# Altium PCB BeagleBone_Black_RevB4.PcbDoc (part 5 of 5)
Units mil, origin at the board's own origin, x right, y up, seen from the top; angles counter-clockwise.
Board outline 3401 x 2151 mil, 6 copper layers (TOP, LYR2_GND, LYR3, LYR4, LYR5_PWR, BOTTOM), stack 62 mil thick; 381 components, 310 nets, 1705 pads, 850 vias.
Unrouted connection lines stored in the file: 1.
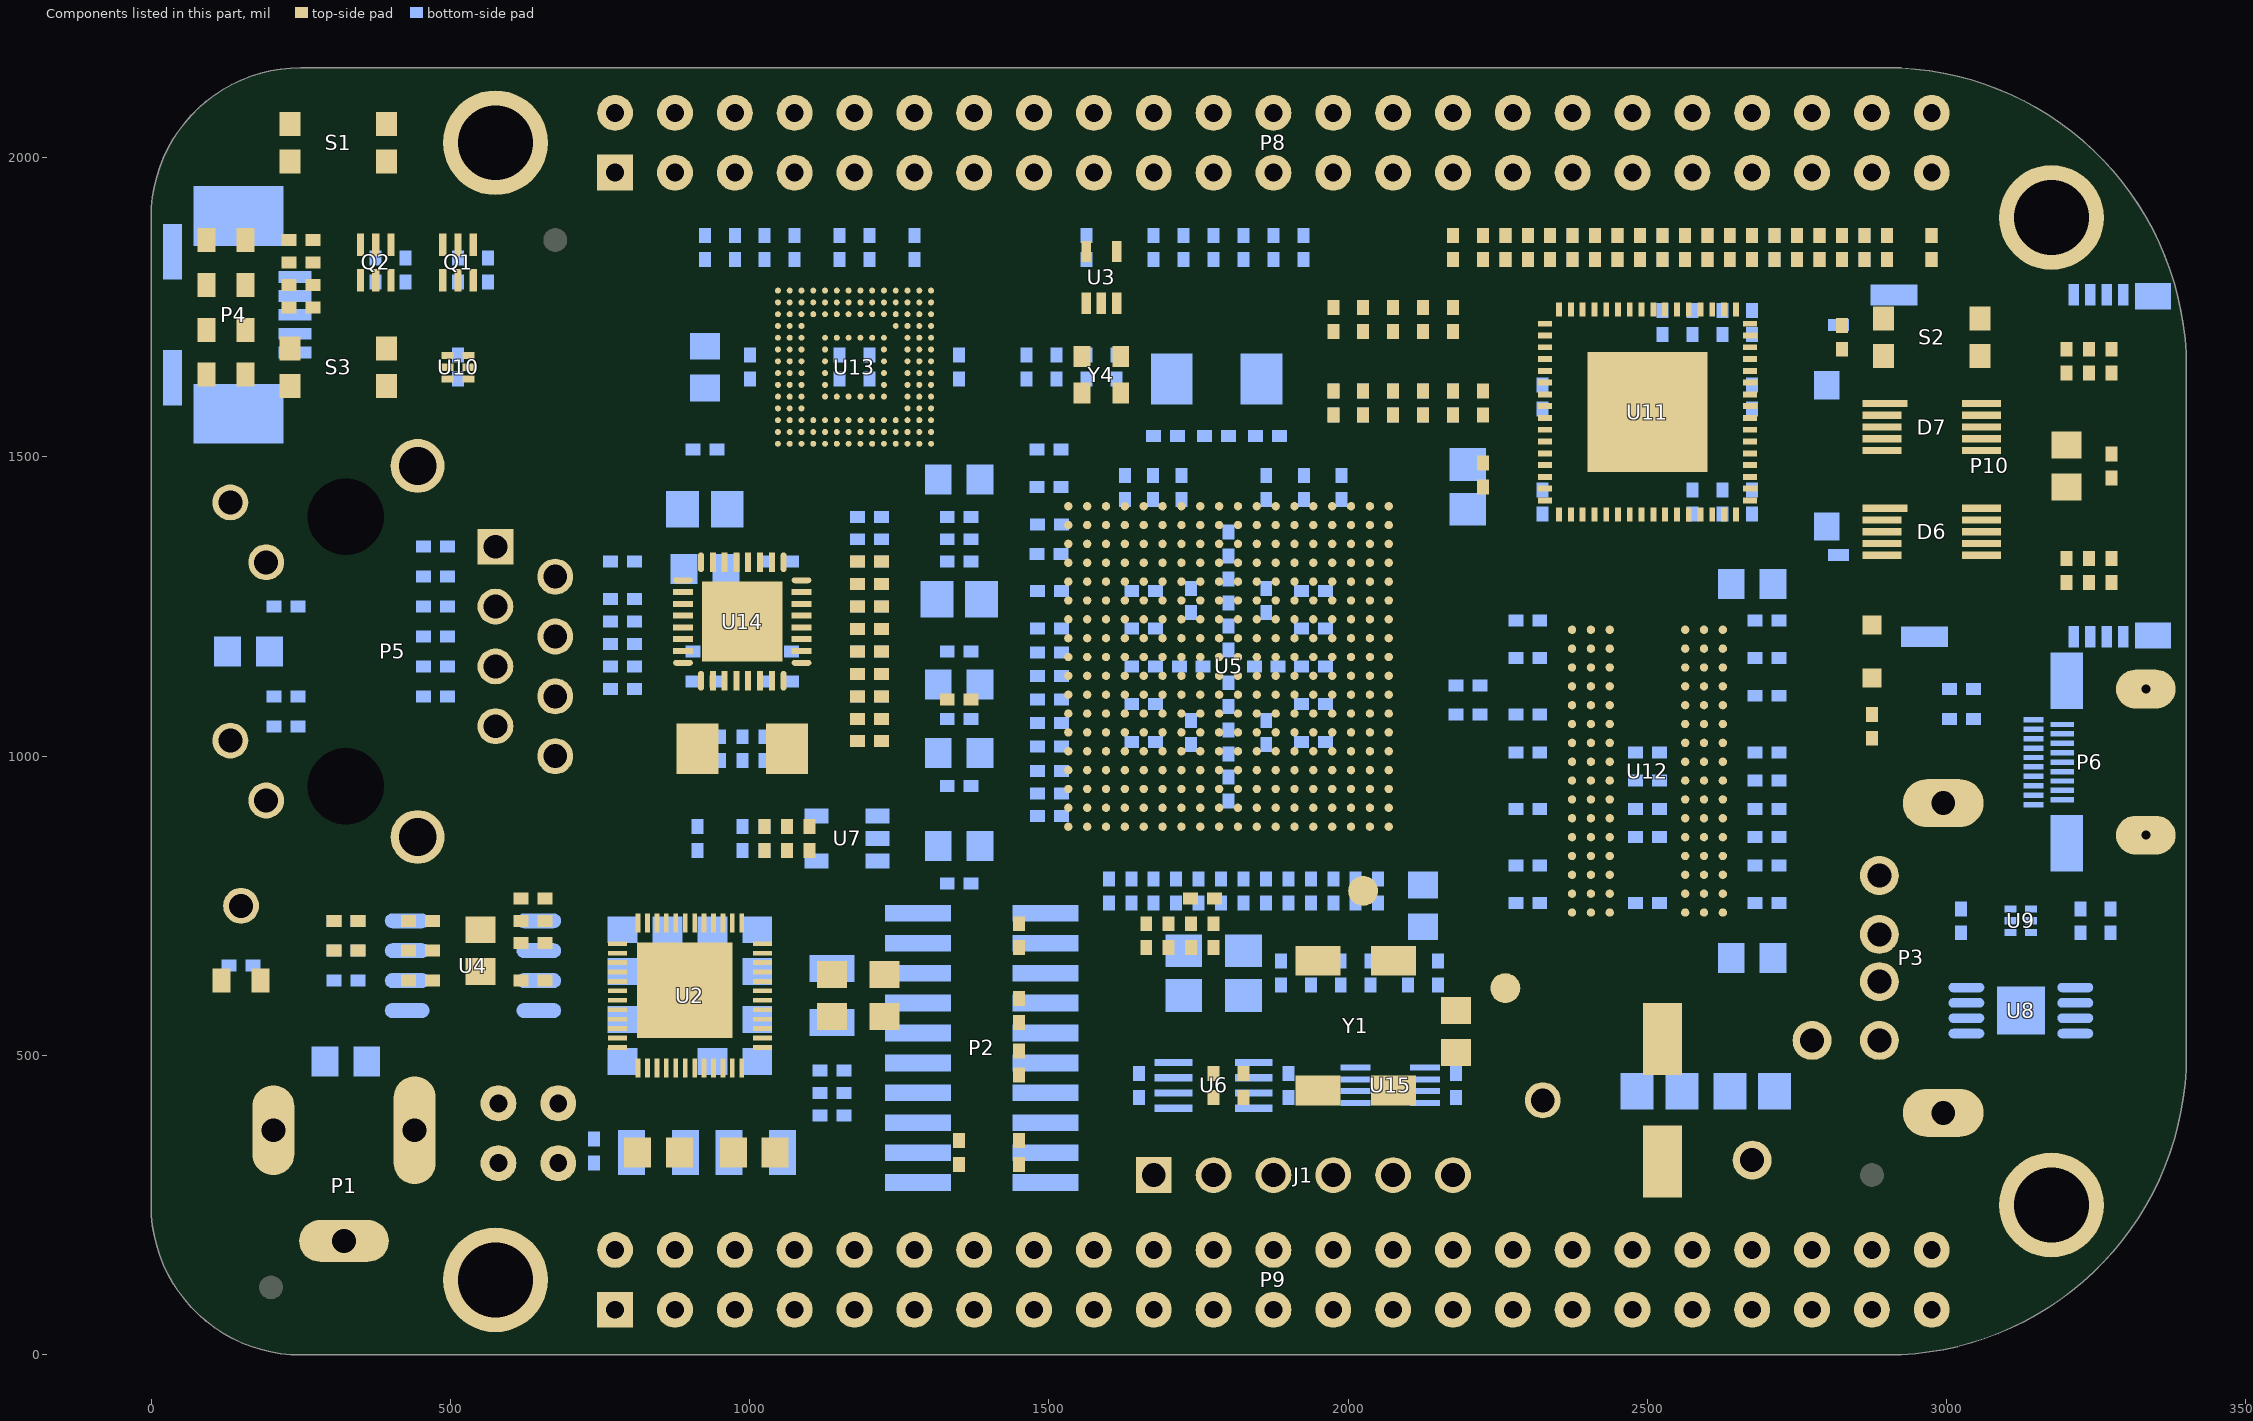
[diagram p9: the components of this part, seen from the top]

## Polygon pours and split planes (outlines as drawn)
no net on Bottom Overlay "Bottom Overlay-No Net" (solid): 47 vertices, not listed, extent 539.79,828.78 590.56,915.78
no net on Bottom Overlay "Bottom Overlay-No Net" (solid): 33 vertices, not listed, extent 603.12,829.78 668.46,915.78
no net on Bottom Overlay "Bottom Overlay-No Net" (solid): 704.91,870.75 ccw(c608.27,870.75) 608.27,967.39 ccw(c608.27,870.75) 511.63,870.75 ccw(c608.27,870.75) 608.27,774.11 ccw(c608.27,870.75) 704.91,870.75
no net on Bottom Overlay "Bottom Overlay-No Net" (solid): 2177.5,492.5 2727.5,492.5 2727.5,617.5 2177.5,617.5 2177.5,492.5
no net on TITLE_BLOCK "TITLE_BLOCK-No Net" (solid): 3550,-50 3450,-50 3450,-150 3400,-150 3400,0 3550,0 3550,-50
no net on TITLE_BLOCK "TITLE_BLOCK-No Net" (solid): 3450,2300 3450,2200 3550,2200 3550,2150 3400,2150 3400,2300 3450,2300
no net on TITLE_BLOCK "TITLE_BLOCK-No Net" (solid): -150,2200 -50,2200 -50,2300 0,2300 0,2150 -150,2150 -150,2200
no net on TITLE_BLOCK "TITLE_BLOCK-No Net" (solid): -50,-150 -50,-50 -150,-50 -150,0 0,0 0,-150 -50,-150
GND_EARTH on BOTTOM "BOTTOM-GND_EARTH" (solid, remove dead copper, pour order 2098): 92 vertices, not listed, extent 25,25 3375,2125
VDDS on BOTTOM "BOTTOM-VDDS 3" (solid, pour order 1441): 107 vertices, not listed, extent 1825,1300 1885,1435
VDDS on BOTTOM "BOTTOM-VDDS 4" (solid, pour order 1442): 212 vertices, not listed, extent 1515,890 1655,1035
VDD_3V3B on BOTTOM "BOTTOM-VDD_3V3B 28" (solid, pour order 2053): 29 vertices, not listed, extent 950,1320.2 1037.5,1437.5
VDD_3V3A on BOTTOM "BOTTOM-VDD_3V3A 24" (solid, pour order 2120): 111 vertices, not listed, extent 1650,1300 1710,1435
VDD_3V3A on BOTTOM "BOTTOM-VDD_3V3A 25" (solid, pour order 2121): 236 vertices, not listed, extent 1890,1300 1998.29,1435
VDD_3V3A on BOTTOM "BOTTOM-VDD_3V3A 26" (solid, pour order 2123): 96 vertices, not listed, extent 1520,1085 1650,1170
VDD_PLL on BOTTOM "BOTTOM-VDD_PLL" (solid, pour order 2296): 167 vertices, not listed, extent 1870,790 1920,1000
VDD_PLL on BOTTOM "BOTTOM-VDD_PLL 1" (solid, pour order 2298): 76 vertices, not listed, extent 1711.26,1300 1775,1435
VDD_PLL on BOTTOM "BOTTOM-VDD_PLL 2" (solid, pour order 2299): 62 vertices, not listed, extent 1515,1065 1615,1110
GND_OSC0 on BOTTOM "BOTTOM-GND_OSC0" (solid, pour order 2604): 31 vertices, not listed, extent 1640,1530 1920,1700
DGND on BOTTOM "BOTTOM-DGND" (solid, pour order 2617): 1625,1200 1630,1205 1630,1220 1650,1220 1650,1205 1660,1195 1660,1170 1650,1160 1650,1145 1625,1145 1625,1200
DGND on BOTTOM "BOTTOM-DGND 1" (solid, pour order 2618): 46 vertices, not listed, extent 770,472.5 1035,642.5
GND_OSC1 on TOP "TOP-GND_OSC1" (solid, pour order 2562): 169 vertices, not listed, extent 1900,390 2125,710
VDD_5V on TOP "TOP-VDD_5V" (solid, pour order 2318): 430,360 410,380 410,528.88 430,548.88 758.4,548.9 758.4,540.9 752.3,540.9 691.45,480 530,480 510,460 510,380 490,360
GND_EARTH on TOP "TOP-GND_EARTH" (solid, remove dead copper, pour order 2089): 91 vertices, not listed, extent 25,25 3375,2125
VDCDC1 on TOP "TOP-VDCDC1" (solid, pour order 1461): 18 vertices, not listed, extent 780,375 911.8,479.82
VDD_MPU on TOP "TOP-VDD_MPU 6" (solid, pour order 2144): 992.5,462.5 985,462.5 985,487.5 1012.5,487.5 1045,455 1100,455 1100,440 1075,415 1075,340 1065,330 1035,330 1020,345 1020,435 992.5,462.5
P_L3 on TOP "TOP-P_L3" (solid, pour order 2228): 18 vertices, not listed, extent 1020,600 1160,700
P_L2 on TOP "TOP-P_L2" (solid, pour order 2246): 970,375 960,385 960,420 965,425 965,439.42 966.14,440.56 966.14,452.36 970.25,456.48 973.52,456.48 1005,425 1005,385 995,375 970,375
P_L1 on TOP "TOP-P_L1" (solid, pour order 2268): 935,437.5 935,385 925,375 880,375 870,385 870,395 875,400 890,400 912.76,422.76 912.76,435.26 925,447.5 935,437.5
VDD_CORE on TOP "TOP-VDD_CORE" (solid, pour order 2466): 28 vertices, not listed, extent 1020,500 1240,584.72
DGND on TOP "TOP-DGND" (solid, pour order 2619): 21 vertices, not listed, extent 1525,1550 1650,1720
VDDS_DDR on LYR3 "LYR3-VDDS_DDR" (solid, pour order 1574): 382 vertices, not listed, extent 725,100 2375,340
VDD_MPU on LYR3 "LYR3-VDD_MPU" (solid, pour order 2143): 375 vertices, not listed, extent 1410,820 1790,1064.98
VDD_1V8 on LYR3 "LYR3-VDD_1V8" (solid, pour order 2377): 134 vertices, not listed, extent 1290,1270 1660,1360
VDD_CORE on LYR3 "LYR3-VDD_CORE" (solid, pour order 2465): 810 vertices, not listed, extent 1260,940 1945,1325
VRTC on LYR3 "LYR3-VRTC" (solid, pour order 2541): 104 vertices, not listed, extent 1855,815 1945,970
VRTC on LYR5_PWR "LYR5_PWR-VRTC" (solid, remove dead copper, pour order 2128): 1855,810 1865,800 1950,800 1970,820 1970,962.5 1957.5,975 1865,975 1855,965
VDDS on LYR5_PWR "LYR5_PWR-VDDS 2" (solid, remove dead copper, pour order 2126): 1630,985 1635,980 1665,980 1695,1010 1840,1010 1845,1015 1845,1050 1820,1075 1685,1075 1670,1060 1670,1040 1630,1000
VDD_PLL on LYR5_PWR "LYR5_PWR-VDD_PLL" (solid, remove dead copper, pour order 2124): 19 vertices, not listed, extent 1600,985 1935,1140
HDMI_1V8 on LYR5_PWR "LYR5_PWR-HDMI_1V8" (solid, pour order 2122): 2130,1370 2130,1755 2140,1765 2330,1765 2365,1800 2675,1800 2710,1765 2760,1765 2770,1755 2770,1370 2760,1360 2140,1360
VDD_1V8 on LYR5_PWR "LYR5_PWR-VDD_1V8 1" (solid, pour order 2119): 17 vertices, not listed, extent 1040,680 1330,1350
VDD_PHYA on LYR5_PWR "LYR5_PWR-VDD_PHYA" (solid, remove dead copper, pour order 2117): 21 vertices, not listed, extent 75,875 920,1475
VDDS_DDR on LYR5_PWR "LYR5_PWR-VDDS_DDR" (solid, pour order 2114): 19 vertices, not listed, extent 1945,212.5 2775,1350
VDD_1V8 on LYR5_PWR "LYR5_PWR-VDD_1V8" (solid, pour order 2111): 1760,550 1760,990 1770,1000 1840,1000 1845,995 1845,805 1860.5,789.5 1925.5,789.5 1935,780 1935,550 1925,540 1770,540
SYS_5V on LYR5_PWR "LYR5_PWR-SYS_5V" (solid, pour order 2109): 29 vertices, not listed, extent 1025,50 3312.5,962.5
VDD_3V3A on LYR5_PWR "LYR5_PWR-VDD_3V3A" (solid, pour order 2106): 77 vertices, not listed, extent 840,210 2890,1865
VDD_3V3B on LYR5_PWR "LYR5_PWR-VDD_3V3B" (solid, remove dead copper, pour order 2104): 87 vertices, not listed, extent 75,50 3312.5,2100
GND_EARTH on LYR5_PWR "PWR-GND_EARTH" (solid, pour order 2096): 91 vertices, not listed, extent 25,25 3375,2125
VDDS on LYR4 "LYR4-VDDS" (solid, pour order 1440): 569 vertices, not listed, extent 1800,945 1945,1369.98
VDD_PLL on LYR4 "LYR4-VDD_PLL" (solid, pour order 2297): 157 vertices, not listed, extent 1510,1065 1619.98,1250
VDD_1V8 on LYR4 "LYR4-VDD_1V8" (solid, pour order 2376): 1247 vertices, not listed, extent 1565,980 2170,1440
DGND on LYR2_GND "GND-DGND" (solid, remove dead copper, pour order 2101): 77 vertices, not listed, extent 75,50 3312.5,2100
GND_EARTH on LYR2_GND "GND-GND_EARTH" (solid, pour order 2091): 91 vertices, not listed, extent 25,25 3375,2125

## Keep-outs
TOP:
  circle w1: c675,1862.5 r62.5
  circle w1: c2875,300 r62.5
  circle w1: c200,112.5 r62.5
BOTTOM:
  circle w1: c2875,300 r62.5
  circle w1: c675,1862.5 r62.5
  circle w1: c200,112.5 r62.5

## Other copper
TOP:
  rectangle net GND_EARTH: 3325,1637.5 3375,1657.5
  text "LAYER 1" at 1000,-700 h55
  text "COMPONENT" at 1000,-800 h55
LYR2_GND:
  rectangle net GND_EARTH: 3325,1637.5 3375,1657.5
  text "LAYER 2" at 1000,-700 h55
  text "GROUND" at 1000,-800 h55
LYR3:
  text "LAYER 3" at 1000,-700 h55
  text "SIGNAL" at 1000,-800 h55
LYR4:
  text "LAYER 4" at 1000,-700 h55
  text "SIGNAL" at 1000,-800 h55
LYR5_PWR:
  rectangle: 3325,1637.5 3375,1657.5
  text "LAYER 5" at 1000,-700 h55
  text "POWER" at 1000,-800 h55
BOTTOM:
  rectangle net GND_EARTH: 45,1884.5 81,1952.9
  rectangle net GND_EARTH: 3325,1645 3375,1665
  text "PCB RevB4" at 87.5,212.5 h40 r270
  text "LAYER 6" at 1000,-700 h55
  text "SOLDER" at 1000,-800 h55
Multi-Layer:
  lines w1: 343.7,-768.7 275,-700 364.5,-610.5 ; 346.8,-864.2 ccw(c357.67,-864.2) 349.9,-871.8 ; 347,-864.2 347,-756.2 ; 347,-862.5 347,-756.2 ; 350,-871.7 374.5,-896.5 ; 374.4,-896.6 ccw(c390.5,-880.26) 390.5,-903.2 ; 378.2,-803 425,-850 575,-700 425,-550 386.5,-588.5 ; 390,-903 462.5,-903 390.5,-903 ; 425,-903 425,-950 ; 425,-871.7 425,-643.7 ; 425,-609.2 425,-515.5 ; 425,-484.2 425,-450 ; 434.5,-609.2 453,-609.2 ; 437.5,-640.5 453,-640.5 ; 453,-515.7 ccw(c453,-500) 468.7,-500 ccw(c453,-500) 453,-484.3 ; 462.5,-903.2 ccw(c462.5,-887.5) 478.2,-887.5 ccw(c462.5,-887.5) 462.5,-871.8 ; 175,-700 675,-700 ; 175,-700 425,-450 ; 175,-700 425,-950 ; 347,-756.2 368.7,-734.2 ; 347,-756.2 368.7,-734.2 ; 368.7,-734.2 378.2,-734.2 ; 368.7,-734.2 378.2,-734.2 ; 378.2,-856.2 378.2,-734.2 ; 378.2,-856.2 393.7,-871.7 ; 378.2,-856.2 393.7,-871.7 ; 378.2,-856.2 378.2,-734.2 ; 378.2,-581.2 378.2,-543.7 ; 378.2,-581.2 406.2,-609.2 ; 378.2,-581.2 378.2,-543.7 ; 378.2,-581.2 406.2,-609.2 ; 378.2,-543.7 406.2,-515.5 ; 378.2,-543.7 406.2,-515.5 ; 393.7,-871.7 462.5,-871.7 393.7,-871.7 ; 406.2,-609.2 453,-609.2 ; 406.2,-609.2 453,-609.2 ; 406.2,-515.5 453,-515.5 406.2,-515.5 ; 425,-950 675,-700 ; 425,-450 675,-700 ; 453,-640.5 403.2,-640.5 453,-640.5 ; 468.7,-625 cw(c453,-625) 453,-640.7 ccw(c453,-625) 468.7,-625 ; 468.7,-625 ccw(c453,-625) 453,-609.3 cw(c453,-625) 468.7,-625 ; 346.8,-589.2 ccw(c357.67,-589.2) 349.9,-596.8 cw(c357.67,-589.2) 346.8,-589.2 ; 346.8,-540.5 cw(c369.74,-540.5) 353.4,-524.4 ccw(c369.74,-540.5) 346.8,-540.5 ; 347,-589.2 347,-540.5 347,-589.2 ; 350,-700 425,-625 500,-700 425,-775 350,-700 ; 350,-596.7 387.2,-634 350,-596.7 ; 353.5,-524.5 387.5,-490.5 353.5,-524.5 ; 387.1,-634.1 ccw(c403.2,-617.76) 403.2,-640.7 cw(c403.2,-617.76) 387.1,-634.1 ; 387.6,-490.6 cw(c402.5,-505.75) 402.5,-484.5 ccw(c402.5,-505.75) 387.6,-490.6 ; 402.5,-484.2 453,-484.2 402.5,-484.2
  lines w20: -5.1,-1127.9 3419.9,-1127.9 ; -5.1,-1127.9 -5.1,-302.9 ; -5.1,-1127.9 3419.9,-1127.9 ; -5.1,-1127.9 -5.1,-302.9 ; -5.1,-302.9 3419.9,-302.9 ; -5.1,-302.9 3419.9,-302.9 ; 3419.9,-1127.9 3419.9,-302.9 ; 3419.9,-1127.9 3419.9,-302.9 ; 894.9,-1127.9 894.9,-302.9 894.9,-1127.9 ; 894.9,-852.9 3419.9,-852.9 894.9,-852.9 ; 894.9,-577.9 3419.9,-577.9 894.9,-577.9 ; 1669.9,-852.9 1669.9,-577.9 1669.9,-852.9
  lines w30: 275,-762.5 362.5,-762.5 362.5,-700 425,-637.5 487.5,-700 487.5,-762.5 562.5,-762.5 ; 312.5,-762.5 262.5,-762.5 225,-725 225,-675 262.5,-637.5 312.5,-637.5 ; 362.5,-725 487.5,-725 ; 512.5,-637.5 550,-637.5 ; 537.5,-762.5 537.5,-637.5 587.5,-637.5 625,-675 625,-725 587.5,-762.5 537.5,-762.5
  text "Circuit Co." at 994.9,-502.9 h100
  text "Circuit Co." at 994.9,-502.9 h100
  text "BeagleBone Black Rev B4" at 1725,-750 h75
  text "BeagleBone Black Rev B4" at 1725,-750 h75
  text "DATE:" at 1025,-1055 h100
  text "DATE:" at 1025,-1055 h100
  text "04/02/2013" at 1600,-1055 h100
  text "04/02/2013" at 1600,-1055 h100

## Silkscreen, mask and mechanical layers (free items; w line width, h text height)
Top Overlay:
  lines w5: 1175,0 1175,37.5 ; 1175,212.5 1175,250 ; 1175,1900 1175,1937.5 ; 1175,2112.5 1175,2150 ; 1250,1075 1300,1125 ; 1250,1300 1300,1350 ; 1675,0 1675,37.5 ; 1675,212.5 1675,250 ; 1675,1900 1675,1937.5 ; 1675,2112.5 1675,2150 ; 2175,0 2175,37.5 ; 2175,212.5 2175,250 ; 2175,1900 2175,1937.5 ; 2175,2112.5 2175,2150 ; 2675,0 2675,37.5 ; 2675,212.5 2675,250 ; 2675,1900 2675,1937.5 ; 2675,2112.5 2675,2150
  text "RESET" at 290,2095 h28
  text "USER LEDS" at 15,1915 h28
  text "0" at 25,1830 h28
  text "1" at 25,1755 h28
  text "2" at 25,1680 h28
  text "3" at 25,1605 h28
  text "POWER" at 295,1550 h28
  text "USB" at 25,1525 h40
  text "AM335x" at 1870,1455 h40
  text "microSD Card" at 3375,1255 h40 r90
  text "HDMI" at 3225,987.5 h40
  text "10/100 Ethernet" at 820,875 h40 r90
  text "PWR" at 62.5,587.5 h28 r90
  text "USB Host" at 3065,355 h40
  text "TSLK" at 1000,-750 h80
  text "TSLKC" at 1000,-750 h80
Bottom Overlay:
  drawing of 2121 lines, arcs and shapes, not listed
  text "S/N" at 2850,570 h40
  text "BSLK" at 1000,-750 h80
  text "BSLKC" at 1000,-750 h80
Top Solder:
  text "SMC" at 1000,-750 h80
Bottom Solder:
  text "SMS" at 1000,-750 h80
FAB:
  drawing of 1884 lines, arcs and shapes, not listed
  text "DRILL CHART: TOP to BOTTOM" at 320,6027.5 h125
  text "ALL UNITS ARE IN MILS" at 795,5847.5 h100
  text "FIGURE" at -925,5712.5 h100
  text "SIZE" at 265,5712.5 h100
  text "TOLERANCE" at 1575,5712.5 h100
  text "PLATED" at 2955,5712.5 h100
  text "QTY" at 3885,5712.5 h100
  text "6.0" at 260,5527.5 h125
  text "+3.0/-3.0" at 1470,5527.5 h125
  text "PLATED" at 2880,5527.5 h125
  text "27" at 3890,5527.5 h125
  text "8.0" at 260,5317.5 h125
  text "+3.0/-3.0" at 1470,5317.5 h125
  text "PLATED" at 2880,5317.5 h125
  text "794" at 3840,5317.5 h125
  text "12.0" at 210,5107.5 h125
  text "+3.0/-3.0" at 1470,5107.5 h125
  text "PLATED" at 2880,5107.5 h125
  text "30" at 3890,5107.5 h125
  text "30.0" at 210,4897.5 h125
  text "+3.0/-3.0" at 1470,4897.5 h125
  text "PLATED" at 2880,4897.5 h125
  text "96" at 3890,4897.5 h125
  text "40.0" at 210,4687.5 h125
  text "+3.0/-3.0" at 1470,4687.5 h125
  text "PLATED" at 2880,4687.5 h125
  text "26" at 3890,4687.5 h125
  text "63.0" at 210,4477.5 h125
  text "+3.0/-3.0" at 1470,4477.5 h125
  text "PLATED" at 2880,4477.5 h125
  text "2" at 3940,4477.5 h125
  text "125.0" at 160,4267.5 h125
  text "+3.0/-3.0" at 1470,4267.5 h125
  text "PLATED" at 2880,4267.5 h125
  text "4" at 3940,4267.5 h125
  text "128.0" at 160,4057.5 h125
  text "+5.0/-5.0" at 1470,4057.5 h125
  text "NON-PLATED" at 2680,4057.5 h125
  text "2" at 3940,4057.5 h125
  text "50.0x15.0" at -40,3847.5 h125
  text "+3.0/-3.0" at 1470,3847.5 h125
  text "PLATED" at 2880,3847.5 h125
  text "2" at 3940,3847.5 h125
  text "95.0x40.0" at -40,3637.5 h125
  text "+3.0/-3.0" at 1470,3637.5 h125
  text "PLATED" at 2880,3637.5 h125
  text "2" at 3940,3637.5 h125
  text "120.0x40.0" at -90,3427.5 h125
  text "+3.0/-3.0" at 1470,3427.5 h125
  text "PLATED" at 2880,3427.5 h125
  text "1" at 3940,3427.5 h125
  text "120.0x40.0" at -90,3217.5 h125
  text "+3.0/-3.0" at 1470,3217.5 h125
  text "PLATED" at 2880,3217.5 h125
  text "1" at 3940,3217.5 h125
  text "140.0x40.0" at -90,3007.5 h125
  text "+3.0/-3.0" at 1470,3007.5 h125
  text "PLATED" at 2880,3007.5 h125
  text "1" at 3940,3007.5 h125
  text "APPROVED" at 11530.1,-7272.1 h100
  text "CIRCUITCO." at 14994.9,-7452.9 h175
  text "CIRCUITCO." at 14994.9,-7452.9 h175
  text "CHECKED" at 11530.1,-7522.1 h100
  text "CalCad" at 12910,-7770 h100
  text "CalCad" at 12910,-7770 h100
  text "DRAFTING" at 11530.1,-7772.1 h100
  text "DATE" at 8505.1,-8022.1 h100
  text "ENGR" at 11530.1,-8022.1 h100
  text "04/02/13" at 9950,-8025 h100
  text "04/02/13" at 9950,-8025 h100
  text "FABRICATION DRAWING," at 14094.9,-8052.9 h150
  text "FABRICATION DRAWING," at 14094.9,-8052.9 h150
  text "DESIGN ENGR" at 8505.1,-8272.1 h100
  text "BeagleBone Black" at 14094.9,-8352.9 h150
  text "BeagleBone Black" at 14094.9,-8352.9 h150
  text "PROJECT ENGR" at 8505.1,-8522.1 h100
  text "ENGR MGR" at 8505.1,-8772.1 h100
  text "NONE" at 14880.1,-8772.1 h100
  text "PCB REV B4" at 16394.9,-8952.9 h150
  text "PCB REV B4" at 16394.9,-8952.9 h150
  text "NEXT ASSEMBLY" at 9230.1,-9022.1 h100
  text "1 OF 1" at 14880.1,-9022.1 h100
ASSY:
  drawing of 15196 lines, arcs and shapes, not listed
  text "RESET" at -9928,9502.64 h80
  text "2" at -8338,9372.64 h80
  text "46" at 1062,9372.64 h80
  text "46" at 4858.68,9372.64 h80
  text "2" at 14368.68,9372.64 h80
  text "1" at -9388,9322.64 h80
  text "S1" at -10688,9172.64 h150
  text "P8" at 1062,9122.64 h150
  text "P8" at 4758.68,9122.64 h150
  text "P4" at 16468.68,9002.64 h150
  text "1" at -8338,8922.64 h80
  text "45" at 1062,8922.64 h80
  text "45" at 4858.68,8922.64 h80
  text "1" at 14368.68,8922.64 h80
  text "R72" at -9908,8802.64 h80
  text "USER LEDS" at -11028,8782.64 h80
  text "R95" at 52,8702.64 h80
  text "R103" at 12906.68,8685.32 h80
  text "R73" at -9908,8662.64 h80
  text "P" at -6948,8662.64 h80
  text "A" at -5928,8662.64 h80
  text "D2" at -11048,8592.64 h80
  text "R77" at 15028.68,8552.64 h80 r90
  text "R76" at 15228.68,8552.64 h80 r90
  text "R79" at 15568.68,8552.64 h80 r90
  text "R78" at 15768.68,8552.64 h80 r90
  text "0" at -10988,8442.64 h80
  text "U13" at -7988,8422.64 h150
  text "5" at 16068.68,8402.64 h80
  text "C165" at -4428,8382.64 h80 r90
  text "C57" at -4208,8382.64 h80 r90
  text "R81" at -4068,8382.64 h80 r90
  text "R80" at -3928,8382.64 h80 r90
  text "R84" at -3788,8382.64 h80 r90
  text "R82" at -3648,8382.64 h80 r90
  text "R83" at -3508,8382.64 h80 r90
  text "R85" at -3368,8382.64 h80 r90
  text "R86" at -3228,8382.64 h80 r90
  text "R87" at -3088,8382.64 h80 r90
  text "R88" at -2948,8382.64 h80 r90
  text "R89" at -2808,8382.64 h80 r90
  text "R90" at -2668,8382.64 h80 r90
  text "R91" at -2528,8382.64 h80 r90
  text "R75" at 712,8382.64 h80 r90
  text "C76" at 5658.68,8372.64 h80 r90
  text "C75" at 8508.68,8372.64 h80 r90
  text "C173" at 1012,8362.64 h80 r90
  text "C158" at 10848.68,8362.64 h80 r90
  text "Q1" at -8748,8342.64 h80 r90
  text "P10" at 3788.68,8342.64 h150
  text "Q2" at -9288,8322.64 h80 r90
  text "R101" at 8708.68,8322.64 h80 r90
  text "R105" at 8848.68,8322.64 h80 r90
  text "R102" at 8988.68,8322.64 h80 r90
  text "R110" at 9128.68,8322.64 h80 r90
  text "R106" at 9268.68,8322.64 h80 r90
  text "R109" at 9408.68,8322.64 h80 r90
  text "C125" at 12008.68,8322.64 h80 r90
  text "R162" at 12328.68,8322.64 h80 r90
  text "R104" at 12828.68,8322.64 h80 r90
  text "R107" at 13708.68,8322.64 h80 r90
  text "C171" at 5206,8320.64 h80 r90
  text "D3" at -11048,8292.64 h80
  text "C61" at 212,8222.64 h80
  text "R108" at 13128.68,8202.64 h80
  text "1" at -5328,8182.64 h80
  text "64" at -1788,8182.64 h80
  text "49" at -568,8182.64 h80
  text "S2" at 672,8182.64 h150
  text "1" at -10988,8142.64 h80
  text "U3" at -4528,8142.64 h80
  text "R74" at -9908,8102.64 h80
  text "R92" at -188,8022.64 h80 r90
  text "R93" at -28,8022.64 h80 r90
  text "R94" at 112,8022.64 h80 r90
  text "C126" at 13308.68,8022.64 h80
  text "1" at 1252,8002.64 h80
  text "D4" at -11048,7992.64 h80
  text "1" at -1988,7972.64 h80
  text "Y2" at 9958.68,7972.64 h150
  text "R71" at -9908,7962.64 h80
  text "R150" at 1762,7962.64 h80 r90
  text "R155" at 1912,7962.64 h80 r90
  text "R151" at 2062,7962.64 h80 r90
  text "R111" at 12668.68,7962.64 h80 r90
  text "R70" at 7308.68,7922.64 h80 r90
  text "R69" at 7458.68,7922.64 h80 r90
  text "R68" at 7608.68,7922.64 h80 r90
  text "R67" at 7758.68,7922.64 h80 r90
  text "R66" at 7908.68,7922.64 h80 r90
  text "R65" at 8058.68,7922.64 h80 r90
  text "R64" at 8208.68,7922.64 h80 r90
  text "R63" at 8358.68,7922.64 h80 r90
  text "R62" at 8508.68,7922.64 h80 r90
  text "R61" at 8658.68,7922.64 h80 r90
  text "R60" at 8808.68,7922.64 h80 r90
  text "R58" at 8958.68,7922.64 h80 r90
  text "R57" at 9108.68,7922.64 h80 r90
  text "R59" at 9258.68,7922.64 h80 r90
  text "R55" at 9408.68,7922.64 h80 r90
  text "R56" at 9558.68,7922.64 h80 r90
  text "R167" at 10808.68,7922.64 h80 r90
  text "C159" at 11008.68,7922.64 h80 r90
  text "R160" at 11208.68,7922.64 h80 r90
  text "2" at -10988,7842.64 h80
  text "R45" at -3768,7842.64 h80 r90
  text "R46" at -3608,7842.64 h80 r90
  text "C168" at -3448,7842.64 h80 r90
  text "C167" at -3288,7842.64 h80 r90
  text "C156" at -2168,7842.64 h80 r90
  text "1" at -9388,7822.64 h80
  text "C149" at 6248.68,7782.64 h80 r90
  text "R149" at 6408.68,7782.64 h80 r90
  text "D5" at -11048,7692.64 h80
  text "Y4" at -4448,7622.64 h80
  text "1" at 16068.68,7622.64 h80
  text "R157" at -128,7602.64 h80
  text "3" at -10988,7542.64 h80
  text "R161" at 11568.68,7522.64 h80 r90
  text "C130" at 12008.68,7522.64 h80 r90
  text "C129" at 12308.68,7522.64 h80 r90
  text "C128" at 12828.68,7522.64 h80 r90
  text "C127" at 13108.68,7522.64 h80 r90
  text "U10" at -9188,7422.64 h80
  text "C148" at 7066,7420.64 h80 r90
  text "C146" at 7266,7420.64 h80 r90
  text "R134" at 12648.68,7342.64 h80
  text "POWER" at -9908,7322.64 h80
  text "C164" at 9508.68,7322.64 h80 r90
  text "C150" at 6726,7320.64 h80 r90
  text "C144" at 7826,7320.64 h80 r90
  text "S3" at -10268,7282.64 h150
  text "R48" at -3928,7282.64 h80 r90
  text "R47" at -3768,7282.64 h80 r90
  text "C166" at -3608,7282.64 h80 r90
  text "C157" at -3448,7282.64 h80 r90
  text "C160" at -3288,7282.64 h80 r90
  text "C163" at -1968,7282.64 h80 r90
  text "C172" at 8408.68,7272.64 h80 r90
  text "R158" at 11058.68,7272.64 h80
  text "R159" at 13208.68,7262.64 h80
  text "C154" at 2052,7242.64 h80 r90
  text "C36" at 15208.68,7242.64 h80 r90
  text "USB" at -10988,7222.64 h150
  text "C26" at 10628.68,7222.64 h80
  text "R145" at 12648.68,7222.64 h80
  text "C25" at 9348.68,7182.64 h80
  text "14" at -5348,7162.64 h80
  text "C77" at 11668.68,7162.64 h80
  text "P5" at -8448,7142.64 h150
  text "R113" at 12648.68,7102.64 h80
  text "C58" at 10388.68,7082.64 h80
  text "R129" at 13868.68,7082.64 h80
  text "D7" at -38,7072.64 h150
  text "C151" at 6488.68,7022.64 h80
  text "C71" at 11088.68,7002.64 h80
  text "R138" at 12648.68,6982.64 h80
  text "U5" at -5088,6942.64 h150
  text "AM335x" at -3608,6942.64 h150
  text "FB4" at 13368.68,6942.64 h80
  text "R123" at 13868.68,6942.64 h80
  text "C153" at 1532,6922.64 h80 r90
  text "C170" at 8808.68,6872.64 h80 r90
  text "C162" at 8958.68,6872.64 h80 r90
  text "C161" at 9108.68,6872.64 h80 r90
  text "R17" at 10108.68,6862.64 h80 r90
  text "R115" at 12648.68,6862.64 h80
  text "C169" at -2288,6802.64 h80 r90
  text "C68" at 9428.68,6802.64 h80 r90
  text "C81" at 9928.68,6802.64 h80 r90
  text "C80" at 10885.6,6802.64 h80 r90
  text "R122" at 13868.68,6802.64 h80
  text "C106" at 10228.68,6762.64 h80 r90
  text "1" at -8788,6742.64 h80
  text "16" at -2028,6742.64 h80
  text "33" at -348,6742.64 h80
  text "C86" at 11088.68,6742.64 h80
  text "R112" at 12648.68,6742.64 h80
  text "V" at -2688,6722.64 h80
  text "C67" at 11388.68,6662.64 h80
  text "R121" at 13868.68,6662.64 h80
  text "R148" at 6368.68,6642.64 h80 r90
  text "C147" at 7108.68,6642.64 h80 r90
  text "C145" at 7808.68,6642.64 h80 r90
  text "R114" at 12648.68,6622.64 h80
  text "C137" at 15108.68,6622.64 h80
  text "U14" at -7348,6542.64 h150
  text "R119" at -6488,6522.64 h80
  text "R139" at -5888,6522.64 h80
  text "17" at -1788,6522.64 h80
  text "32" at -588,6522.64 h80
  text "C38" at 11388.68,6522.64 h80
  text "R120" at 13868.68,6522.64 h80
  text "R117" at 12648.68,6502.64 h80
  text "C118" at 6308.68,6442.64 h80
  text "U11" at -1338,6422.64 h150
  text "C74" at 9308.68,6422.64 h80 r90
  text "C56" at 9928.68,6422.64 h80 r90
  text "R49" at 10788.68,6422.64 h80
  text "R133" at -5888,6372.64 h80
  text "D6" at -38,6372.64 h150
  text "C43" at 9788.68,6362.64 h80 r90
  text "C94" at 10328.68,6362.64 h80 r90
  text "C78" at 11388.68,6362.64 h80
  text "FB5" at 8458.68,6322.64 h80 r90
  text "C41" at 10448.68,6302.64 h80
  text "C73" at 9328.68,6292.64 h80
  text "C138" at 15588.68,6272.64 h80
  text "R128" at -5888,6222.64 h80
  text "C135" at 12808.68,6202.64 h80
  text "U12" at -1338,6172.64 h150
  text "C84" at 10788.68,6172.64 h80
  text "microSD Card" at 2412,6142.64 h150 r90
  text "C42" at 9928.68,6122.64 h80 r90
  text "C133" at 13308.68,6082.64 h80
  text "R127" at -5888,6072.64 h80
  text "C139" at 15588.68,6072.64 h80
  text "FB1" at 11508.68,6062.64 h80 r90
  text "R132" at 16568.68,6062.64 h80
  text "C97" at 9328.68,6042.64 h80
  text "C66" at 10448.68,6042.64 h80
  text "C107" at 8268.68,5982.64 h80
  text "C114" at 6688.68,5962.64 h80
  text "C136" at 12808.68,5942.64 h80
  text "C132" at 13308.68,5932.64 h80
  text "C87" at 10785.68,5924.64 h80
  text "R126" at -5888,5922.64 h80
  text "C51" at 11688.68,5922.64 h80
  text "A" at -1942,5885.64 h80
  text "C141" at 15588.68,5872.64 h80
  text "R154" at 1762,5852.64 h80 r90
  text "R153" at 1912,5852.64 h80 r90
  text "R152" at 2062,5852.64 h80 r90
  text "C47" at 9928.68,5802.64 h80 r90
  text "C46" at 10148.68,5802.64 h80
  text "C65" at 10448.68,5802.64 h80
  text "C98" at 9328.68,5792.64 h80
  text "R125" at -5888,5772.64 h80
  text "C45" at 10785.68,5767.16 h80
  text "D8" at 592,5762.64 h80
  text "C108" at 8268.68,5762.64 h80
  text "C115" at 6688.68,5722.64 h80
  text "R137" at 15588.68,5672.64 h80
  text "C" at -1942,5633.64 h80
  text "R124" at -5888,5622.64 h80
  text "C69" at 10788.68,5622.64 h80
  text "R136" at 17088.68,5602.64 h80 r90
  text "R98" at 7008.68,5542.64 h80
  text "R22" at 8628.68,5542.64 h80
  text "C99" at 9328.68,5542.64 h80
  text "C48" at 9608.68,5542.64 h80
  text "C60" at 10448.68,5542.64 h80
  text "R147" at 5308.68,5522.64 h80
  text "C109" at 7808.68,5482.64 h80
  text "C40" at 11528.68,5482.64 h80 r90
  text "R116" at 12568.68,5472.64 h80
  text "R130" at 16568.68,5462.64 h80
  text "C79" at 10785.68,5452.16 h80
  text "19" at 4708.68,5432.64 h80
  text "C134" at 12908.68,5422.64 h80
  text "C131" at 13308.68,5412.64 h80
  text "C49" at 10188.68,5402.64 h80 r90
  text "C123" at 7008.68,5382.64 h80
  text "C28" at 8628.68,5382.64 h80
  text "R144" at 13848.68,5382.64 h80
  text "E" at -1942,5381.64 h80
  text "R146" at 5308.68,5322.64 h80
  text "C116" at 6208.68,5322.64 h80
  text "C52" at 11388.68,5322.64 h80
  text "R131" at 12568.68,5322.64 h80
  text "C70" at 10448.68,5302.64 h80
  text "C140" at 15108.68,5302.64 h80
  text "C54" at 10785.68,5294.64 h80
  text "C100" at 9278.68,5292.64 h80
  text "R28" at -5848,5282.64 h80
  text "R166" at 512,5282.64 h80
  text "18" at 4128.68,5282.64 h80
  text "R100" at 7008.68,5242.64 h80
  text "R140" at 12568.68,5172.64 h80
  text "C44" at 10785.68,5137.16 h80
  text "G" at -1942,5129.64 h80
  text "C117" at 5788.68,5102.64 h80
  text "C72" at 10188.68,5102.64 h80 r90
  text "R135" at 16108.68,5102.64 h80
  text "HDMI" at 1812,5072.64 h150
  text "R118" at -6488,5022.64 h80
  text "C39" at 11528.68,5022.64 h80 r90
  text "C82" at 10785.68,4972.64 h80
  text "C110" at 7808.68,4942.64 h80
  text "C143" at 13768.68,4932.64 h80 r90
  text "R142" at 13918.68,4932.64 h80 r90
  text "R141" at 14068.68,4932.64 h80 r90
  text "R143" at 14218.68,4932.64 h80 r90
  text "C142" at 14368.68,4932.64 h80 r90
  text "C119" at 5788.68,4902.64 h80
  text "C53" at 11388.68,4882.64 h80
  text "J" at -1942,4877.64 h80
  text "C50" at 9788.68,4842.64 h80 r90
  text "C63" at 10328.68,4842.64 h80 r90
  text "C83" at 10785.68,4822.16 h80
  text "C88" at 10188.68,4782.64 h80 r90
  text "2" at 4248.68,4762.64 h80
  text "R96" at 5788.68,4722.64 h80
  text "C111" at 8268.68,4722.64 h80
  text "Y3" at -7628,4662.64 h150
  text "1" at 4708.68,4632.64 h80
  text "L" at -1942,4625.64 h80
  text "10/100 Ethernet" at -7808,4622.64 h150 r90
  text "A" at -2688,4572.64 h80
  text "C85" at 11088.68,4542.64 h80
  text "R99" at 5788.68,4522.64 h80
  text "C112" at 7808.68,4482.64 h80
  text "R1" at 13768.68,4482.64 h80 r90
  text "C101" at 9058.68,4422.64 h80 r90
  text "R54" at 9208.68,4422.64 h80 r90
  text "R26" at 9358.68,4422.64 h80 r90
  text "C104" at 9508.68,4422.64 h80 r90
  text "C92" at 9658.68,4422.64 h80 r90
  text "C105" at 9808.68,4422.64 h80 r90
  text "C89" at 9958.68,4422.64 h80 r90
  text "C91" at 10108.68,4422.64 h80 r90
  text "C90" at 10258.68,4422.64 h80 r90
  text "C59" at 10408.68,4422.64 h80 r90
  text "R20" at 10558.68,4422.64 h80 r90
  text "R19" at 10708.68,4422.64 h80 r90
  text "R51" at 10858.68,4422.64 h80 r90
  text "1" at -2848,4402.64 h80
  text "C62" at 11508.68,4382.64 h80 r90
  text "N" at -1942,4373.64 h80
  text "18" at -5088,4372.64 h80
  text "C124" at 7008.68,4362.64 h80
  text "C152" at 13028.68,4362.64 h80 r90
  text "R156" at 13448.68,4362.64 h80 r90
  text "C120" at 5788.68,4322.64 h80
  text "C3" at -8628,4262.64 h80
  text "R27" at -4208,4262.64 h80
  text "P6" at 3728.68,4242.64 h150
  text "R97" at 7068.68,4222.64 h80
  text "C64" at 11328.68,4222.64 h80
  text "20" at 11128.68,4202.64 h80 r90
  text "R3" at -6928,4182.64 h80 r90
  text "R4" at -6768,4182.64 h80 r90
  text "U9" at 4628.68,4182.64 h80
  text "C13" at 13328.68,4182.64 h80
  text "U2" at -7628,4162.64 h150
  text "TP3" at -3428,4162.64 h80
  text "C19" at -9928,4122.64 h80
  text "R9" at -9368,4122.64 h80
  text "U7" at 12568.68,4122.64 h80
  text "C14" at 13008.68,4122.64 h80
  text "R11" at 15758.68,4122.64 h80
  text "R" at -1942,4121.64 h80
  text "C37" at -6628,4082.64 h80 r90
  text "C121" at 5788.68,4082.64 h80
  text "C95" at 8528.68,3982.64 h80 r90
  text "19" at 12448.68,3982.64 h80 r90
  text "TP4" at -10728,3962.64 h80 r90
  text "1" at -8068,3962.64 h80
  text "C113" at 7808.68,3922.64 h80
  text "L3" at 12558.68,3922.64 h80
  text "R52" at 4008.68,3862.64 h80 r90
  text "C35" at 4528.68,3862.64 h80 r90
  text "R53" at 5328.68,3862.64 h80 r90
  text "C18" at -8228,3842.64 h80 r90
  text "C32" at -4548,3782.64 h80 r90
  text "R50" at -5088,3772.64 h80 r90
  text "1" at -1620,3737.64 h80
  text "3" at -1368,3737.64 h80
  text "7" at -864,3737.64 h80
  text "9" at -612,3737.64 h80
  text "R8" at -9468,3722.64 h80 r90
  text "C122" at 6868.68,3722.64 h80
  text "C16" at -8688,3693.04 h80
  text "C93" at -3788,3682.64 h80 r90
  text "C20" at 16258.68,3672.64 h80 r90
  text "R10" at -9928,3602.64 h80
  text "D1" at -10188,3582.64 h80
  text "C4" at 14358.68,3572.64 h80 r90
  text "TP2" at -1888,3522.64 h80
  text "R12" at 16458.68,3522.64 h80
  text "PWR" at -10838,3472.64 h80 r90
  text "RT1" at -388,3472.64 h150
  text "C31" at -4248,3442.64 h80 r90
  text "C33" at -4088,3442.64 h80 r90
  text "C17" at 15758.68,3422.64 h80
  text "R7" at -9368,3402.64 h80
  text "C1" at -8968,3402.64 h80
  text "R5" at -8628,3402.64 h80
  text "S/N" at 5808.68,3402.64 h150
  text "C11" at -6738,3372.64 h80 r90
  text "C55" at -5888,3372.64 h80 r90
  text "P2" at 10928.68,3362.64 h150 r90
  text "R24" at -5088,3272.64 h80 r90
  text "FB2" at 9768.68,3262.64 h80
  text "FB3" at 10168.68,3262.64 h80
  text "C15" at 13808.68,3242.64 h80 r90
  text "Y1" at -3688,3222.64 h150
  text "C96" at -2188,3222.64 h80
  text "C22" at 9108.68,3122.64 h80 r90
  text "C21" at 9308.68,3122.64 h80 r90
  text "U4" at 14968.68,3122.64 h80
  text "C103" at 8648.68,3102.64 h80 r90
  text "C102" at 8868.68,3102.64 h80 r90
  text "R164" at 9508.68,3082.64 h80 r90
  text "R163" at 9668.68,3082.64 h80 r90
  text "R14" at 12508.68,3082.64 h80
  text "TP5" at -8928,3022.64 h80
  text "TP7" at -8528,3022.64 h80
  text "C10" at 14358.68,3022.64 h80 r90
  text "C2" at 16208.68,3022.64 h80
  text "U8" at 4988.68,3002.64 h150
  text "R23" at -5088,2922.64 h80 r90
  text "C8" at 13058.68,2822.64 h80
  text "C7" at 13458.68,2822.64 h80
  text "C27" at -4090,2795 h80 r90
  text "R18" at 10828.68,2782.64 h80 r90
  text "TP1" at -2288,2772.64 h80
  text "R21" at 9508.68,2762.64 h80 r90
  text "R165" at -3600,2755 h80 r90
  text "C9" at -7808,2672.64 h80
  text "C12" at -7208,2672.64 h80
  text "J1" at -4538,2622.64 h150
  text "FB7" at 6368.68,2602.64 h80
  text "FB8" at 6988.68,2602.64 h80
  text "U15" at 8768.68,2602.64 h80
  text "USB Host" at 1172,2542.64 h150
  text "C155" at 8408.68,2522.64 h80 r90
  text "U6" at 9848.68,2502.64 h80
  text "C24" at 12508.68,2502.64 h80
  text "C30" at 12508.68,2342.64 h80
  text "C29" at -5788,2322.64 h80 r90
  text "R25" at -5088,2322.64 h80 r90
  text "P3" at 762,2322.64 h150
  text "C34" at -1888,2222.64 h150
  text "2" at 10888.68,2222.64 h80
  text "1" at 12348.68,2202.64 h80
  text "L2" at 13078.68,2122.64 h80
  text "L1" at 13728.68,2122.64 h80
  text "R6" at 14308.68,2102.64 h80 r90
  text "TP6" at -8928,2062.64 h80
  text "TP8" at -8528,2062.64 h80
  text "2" at -8338,1772.64 h80
  text "46" at 1062,1772.64 h80
  text "46" at 4858.68,1772.64 h80
  text "2" at 14368.68,1772.64 h80
  text "P1" at -9938,1522.64 h150
  text "P9" at 1062,1522.64 h150
  text "P9" at 4758.68,1522.64 h150
  text "1" at -8338,1372.64 h80
  text "1" at 14368.68,1372.64 h80
  text "45" at 1062,1322.64 h80
  text "45" at 4858.68,1322.64 h80
  text "ASSEMBLY COMPONENT SIDE" at -8000,0 h250
  text "ASSEMBLY COMPONENT SIDE" at -8000,0 h250
  text "ASSEMBLY SOLDER SIDE" at 7500,0 h250
  text "APPROVED" at 11530.1,-7272.1 h100
  text "CIRCUITCO." at 14994.9,-7452.9 h175
  text "CIRCUITCO." at 14994.9,-7452.9 h175
  text "CHECKED" at 11530.1,-7522.1 h100
  text "DRAFTING" at 11530.1,-7772.1 h100
  text "CalCad" at 12775,-7800 h100
  text "CalCad" at 12775,-7800 h100
  text "DATE" at 8505.1,-8022.1 h100
  text "ENGR" at 11530.1,-8022.1 h100
  text "04/02/13" at 9950,-8025 h100
  text "04/02/13" at 9950,-8025 h100
  text "ASSEMBLY DRAWING," at 14094.9,-8052.9 h150
  text "ASSEMBLY DRAWING," at 14094.9,-8052.9 h150
  text "DESIGN ENGR" at 8505.1,-8272.1 h100
  text "BeagleBone Black" at 14094.9,-8352.9 h150
  text "BeagleBone Black" at 14094.9,-8352.9 h150
  text "PROJECT ENGR" at 8505.1,-8522.1 h100
  text "ENGR MGR" at 8505.1,-8772.1 h100
  text "NONE" at 14875,-8775 h100
  text "NONE" at 14875,-8775 h100
  text "NEXT ASSEMBLY" at 9230.1,-9022.1 h100
  text "1 OF 1" at 14880.1,-9022.1 h100
DRAWING_ORIGIN:
  lines w1: -25,0 25,0 ; 0,-25 0,25 ; 14220,-6890 18295,-6890 ; 14975,-6510 17850,-6510 ; 0,250 ccw(c250,250) 250,0 2900,0 ccw(c2900,500) 3400,500 3400,1650 ccw(c2900,1650) 2900,2150 250,2150 ccw(c250,1900) 0,1900 0,250
  text "This work is licensed under the Creative Commons Attribution-Share Alike 3.0 Unported License." at 12580,-6360 h55
  text "This work is licensed under the Creative Commons Attribution-Share Alike 3.0 Unported License." at 12580,-6360 h55
  text "To view a copy of this license, visit http://creativecommons.org/licenses/by-sa/3.0/ or send" at 12580,-6485 h55
  text "To view a copy of this license, visit http://creativecommons.org/licenses/by-sa/3.0/ or send" at 12580,-6485 h55
  text "a letter to Creative Commons, 171 Second Street, Suite 300, San Francisco, California, 94105, USA." at 12580,-6610 h55
  text "a letter to Creative Commons, 171 Second Street, Suite 300, San Francisco, California, 94105, USA." at 12580,-6610 h55
  text "All derivative works are to be attributed to CircuitCo LLC." at 12580,-6735 h55
  text "All derivative works are to be attributed to CircuitCo LLC." at 12580,-6735 h55
  text "For more information, see http://creativecommons.org/license/results-one?license_code=by-sa" at 12580,-6860 h55
  text "For more information, see http://creativecommons.org/license/results-one?license_code=by-sa" at 12580,-6860 h55
DIMENSION:
  lines w1: -1325,150 -1300,0 ; -1325,150 -1275,150 ; -1325,150 -1300,0 ; -1325,150 -1275,150 ; -1325,2000 -1300,2150 ; -1325,2000 -1275,2000 ; -1325,2000 -1300,2150 ; -1325,2000 -1275,2000 ; -1300,0 -1275,150 ; -1300,0 -1300,751 -1300,0 ; -1300,0 -1275,150 ; -1300,2150 -1275,2000 ; -1300,2150 -1300,1449 -1300,2150 ; -1300,2150 -1275,2000 ; -261.72,2436.5 75,2100 ; -261.72,2436.5 -411.72,2436.5 -261.72,2436.5 ; -261.72,2436.5 75,2100 ; -48.77,2188.35 75,2100 ; -48.77,2188.35 -13.43,2223.71 ; -48.77,2188.35 75,2100 ; -48.77,2188.35 -13.43,2223.71 ; -13.43,2223.71 75,2100 ; -13.43,2223.71 75,2100 ; 0,-1350 150,-1325 ; 0,-1350 150,-1375 ; 0,-1350 1301,-1350 0,-1350 ; 0,-1350 150,-1325 ; 0,-1350 150,-1375 ; 150,-1375 150,-1325 ; 150,-1375 150,-1325 ; 3050,-400 3175,-150 ; 3050,-400 3050,-451 3050,-400 ; 3050,-400 3175,-150 ; 3175,-150 3175,150 3175,-150 ; 3225,2050 3561.72,2386.5 ; 3225,2050 3313.43,2173.71 ; 3225,2050 3348.77,2138.35 ; 3225,2050 3561.72,2386.5 ; 3225,2050 3313.43,2173.71 ; 3225,2050 3348.77,2138.35 ; 3250,-1375 3400,-1350 ; 3250,-1375 3250,-1325 ; 3250,-1375 3400,-1350 ; 3250,-1375 3250,-1325 ; 3250,-1325 3400,-1350 ; 3250,-1325 3400,-1350 ; 3313.43,2173.71 3348.77,2138.35 ; 3313.43,2173.71 3348.77,2138.35 ; 3400,-1350 1999,-1350 3400,-1350 ; 3561.72,2386.5 3711.72,2386.5 3561.72,2386.5 ; -1400,0 -700,0 -1400,0 ; -1400,2150 -1100,2150 -1400,2150 ; -471,0 -100,0 -471,0 ; -456,125 475,125 -456,125 ; -451,2025 475,2025 -451,2025 ; -451,2150 150,2150 -451,2150 ; 0,-1450 0,-700 0,-1450 ; 0,-471 0,-100 0,-471 ; 575,-456 575,25 575,-456 ; 3275,250 3906,250 3275,250 ; 3275,1900 3951,1900 3275,1900 ; 3400,-1450 3400,-1100 3400,-1450 ; 3400,-451 3400,400 3400,-451
  lines w8: -12700,5850 -11150,5850 ; -12650,11350 -11600,11350
  lines w9.8: -12633.8,-51.3 -4033.8,-51.3 ; -12633.8,363.7 -4033.8,363.7 ; -12633.8,1233.8 -4033.8,1233.8 ; -12633.8,1533.8 -4033.8,1533.8 ; -12633.8,2033.8 -4033.8,2033.8 ; -12633.5,-52 -12633.8,2433.8 -4033.8,2433.8 -4033.5,-52 ; -12629.1,158.9 -4033.5,159 ; -12629.1,573.9 -4033.5,574 ; -12629.1,778.6 -4033.5,779 ; -12629.1,978.6 -4033.5,979 ; -9877.5,-52 -9877.5,1534 ; -8777.5,-52 -8777.5,2034 ; -7237.5,-52 -7237.5,2034 ; -5657.5,-52 -5657.5,2034
  text "FAB NOTES:" at -12664.5,11401 h100
  text "1. ALL DIMENSIONS ARE IN INCHES, UNLESS" at -12664.5,11151 h100
  text "OTHERWISE NOTED." at -12664.5,10951 h100
  text "2. THE PWB SHALL BE FABRICATED TO IPC-6012," at -12664.5,10701 h100
  text "CLASS 2 AND WORKMANSHIP SHALL CONFORM TO" at -12664.5,10501 h100
  text "IPC-A-600, CLASS 2. CURRENT REVISIONS." at -12664.5,10301 h100
  text "3. BOARD MATERIAL SHALL BE 180 Tg/350 Td ISOLA FR-370HR" at -12664.5,10051 h100
  text "OR EQUIVALENT, RoHS COMPLIANT AND LEAD FREE" at -12664.5,9851 h100
  text "ASSEMBLY CAPABLE.  BOARD MATERIAL SHALL" at -12664.5,9651 h100
  text "MEET OR EXCEED IPC-4101B. COLOR: NATURAL." at -12664.5,9451 h100
  text "4. BOARD MATERIAL & CONSTRUCTION TO BE U.L." at -12664.5,9201 h100
  text "APPROVED AND MARKED ON THE FINISHED BOARD." at -12664.5,9001 h100
  text "5. MINIMUM COPPER WALL THICKNESS OF PLATED-THRU" at -12664.5,8751 h100
  text "HOLES TO BE .001 INCH, WITH A MINIMUM" at -12664.5,8551 h100
  text "ANNULAR RING OF .002 INCH." at -12664.5,8351 h100
  text "6. OVERALL BOARD THICKNESS TO BE .062 +/- 10%" at -12664.5,8051 h100
  text "AND APPLIES AFTER ALL LAMINATION AND PLATING" at -12664.5,7851 h100
  text "PROCESSES, MEASURED FROM COPPER TO COPPER." at -12664.5,7651 h100
  text "7. MAX. WARP & TWIST TO BE .0075 INCHES PER INCH." at -12664.5,7401 h100
  text "8. BOARD MUST BE ELECTRICALLY TESTED USING" at -12664.5,7151 h100
  text "SUPPLIED IPC-D-356 NETLIST." at -12675,6950 h100
  text "9. ALL VIAS TO HAVE SOLDERMASK." at -12775,6700 h100
  text "FINISHED AS SMOOTH WALL BY VEDOR." at -12685,6100 h100
  text "PROCESS NOTES:" at -12683.5,5902 h100
  text "1. PLATE ALL EXPOSED AREAS WITH ELECTROLESS" at -12682.5,5643 h100
  text "IMMERSION GOLD, NICKEL 150 MICROINCHES THK MIN" at -12682.5,5443 h100
  text "GOLD 5-15 MICROINCHES THK MIN." at -12682.5,5243 h100
  text "2. APPLY LPI SOLDERMASK OVER BARE COPPER (SMOBC)," at -12683.5,5002 h100
  text "COLOR: BLACK. SOLDERMASK SHALL CONFIRM TO IPC-SM-840." at -12683.5,4802 h100
  text "CLASS H. CURRENT REV." at -12683.5,4602 h100
  text "3. SOLDERMASK ARTWORK HAS ZERO (0) OVERSIZED PADS." at -12683.5,4352 h100
  text "FABRICATION VENDOR IS ALLOWED TO ADJUST THE COMPONENT" at -12683.5,4152 h100
  text "SOLDERMASK PADS TO MEET THEIR TOOLING REQUIREMENTS." at -12683.5,3952 h100
  text "4. APPLY LPI SILKSCREEN OR EQUIVALENT PER THE ARTWORK." at -12683.5,3702 h100
  text "COLOR: WHITE." at -12683.5,3502 h100
  text "R.250 2X" at -1350,2375 h100
  text "R.500 2X" at 3761.72,2336.5 h100
  text "R.500 2X" at 3761.72,2336.5 h100
  text "LAYER STACK-UP - ALL DIMENSIONS IN INCHES" at -12489,2143.6 h180
  text "2.150" at -1070,2100 h100
  text "2.150" at -1070,2100 h100
  text "2.025" at -1070,1975 h100
  text "2.025" at -1070,1975 h100
  text "50ohm SINGLE ENDED" at -8702.5,1889 h80
  text "100ohm DIFFERENTIAL" at -5587.5,1884 h80
  text "90ohm DIFFERENTIAL" at -7182.5,1874 h80
  text "1.900" at 4030,1850 h100
  text "1.900" at 4030,1850 h100
  text "IMPEDANCE CONTROL" at -8712.5,1754 h80
  text "IMPEDANCE CONTROL" at -5582.5,1744 h80
  text "IMPEDANCE CONTROL" at -7177.5,1734 h80
  text "+/- 10%" at -8707.5,1619 h80
  text "+/- 10%" at -5582.5,1604 h80
  text "+/- 10%" at -7177.5,1594 h80
  text "COPPER WEIGHT" at -9834.1,1398.9 h80
  text "TRACE WIDTH" at -8378.8,1353.8 h80
  text "TRACE WIDTH / SPACE" at -5617.5,1344 h80
  text "LAYER#" at -11533.8,1333.8 h80
  text "TRACE WIDTH / SPACE" at -7212.5,1334 h80
  text "(OZ)" at -9469.1,1298.9 h55
  text "4.75" at -8246.5,1082 h100
  text "3.75/7.25" at -5402.5,1069 h100
  text "HALF+PLATING" at -9803.8,1063.8 h80
  text "4.5/6.5" at -6857.5,1055 h100
  text "LAYER 1 - PRIMARY SIDE - SIGNAL" at -12533.8,1033.8 h80
  text "1" at -9423.8,858.7 h100
  text "LAYER 2 - GROUND PLANE" at -12533.8,833.8 h80
  text "2.150" at -1250,830 h100 r90
  text "2.150" at -1250,830 h100 r90
  text "5.25" at -8255,645 h100
  text "5.0/7.0" at -6845,640 h100
  text "4.00/8.00" at -5377.5,635 h100
  text "1" at -9416.5,627 h100
  text "LAYER 3 - SIGNAL" at -12526.5,617 h80
  text "5.25" at -8246.5,437 h100
  text "1" at -9407.5,430 h100
  text "5.0/7.0" at -6854.5,430 h100
  text "4.00/8.00" at -5372.5,419 h100
  text "LAYER 4 - SIGNAL" at -12526.5,417 h80
  text "1" at -9416.5,212 h100
  text "LAYER 5 - SPLIT POWER PLANE" at -12526.5,202 h80
  text ".250" at 3985,200 h100
  text ".250" at 3985,200 h100
  text ".125" at -965,75 h100
  text ".125" at -965,75 h100
  text "4.75" at -8246.5,22 h100
  text "4.5/6.5" at -6854.5,15 h100
  text "HALF+PLATING" at -9791.5,12 h80
  text "3.75/7.25" at -5372.5,4 h100
  text "LAYER 6 - SECONDARY SIDE - SIGNAL" at -12526.5,2 h80
  text "0" at -650,-50 h100
  text "0" at -650,-50 h100
  text "0" at -50,-650 h100
  text "0" at -50,-650 h100
  text ".575" at 625,-965 h100 r90
  text ".575" at 625,-965 h100 r90
  text "3.175" at 3100,-1070 h100 r90
  text "3.175" at 3100,-1070 h100 r90
  text "3.400" at 3450,-1070 h100 r90
  text "3.400" at 3450,-1070 h100 r90
  text "3.400" at 1380,-1400 h100
  text "3.400" at 1380,-1400 h100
